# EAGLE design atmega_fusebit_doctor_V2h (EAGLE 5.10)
AUTHOR: PAWEL KISIELEWSKI (MANEKINEN); REV: 2.0
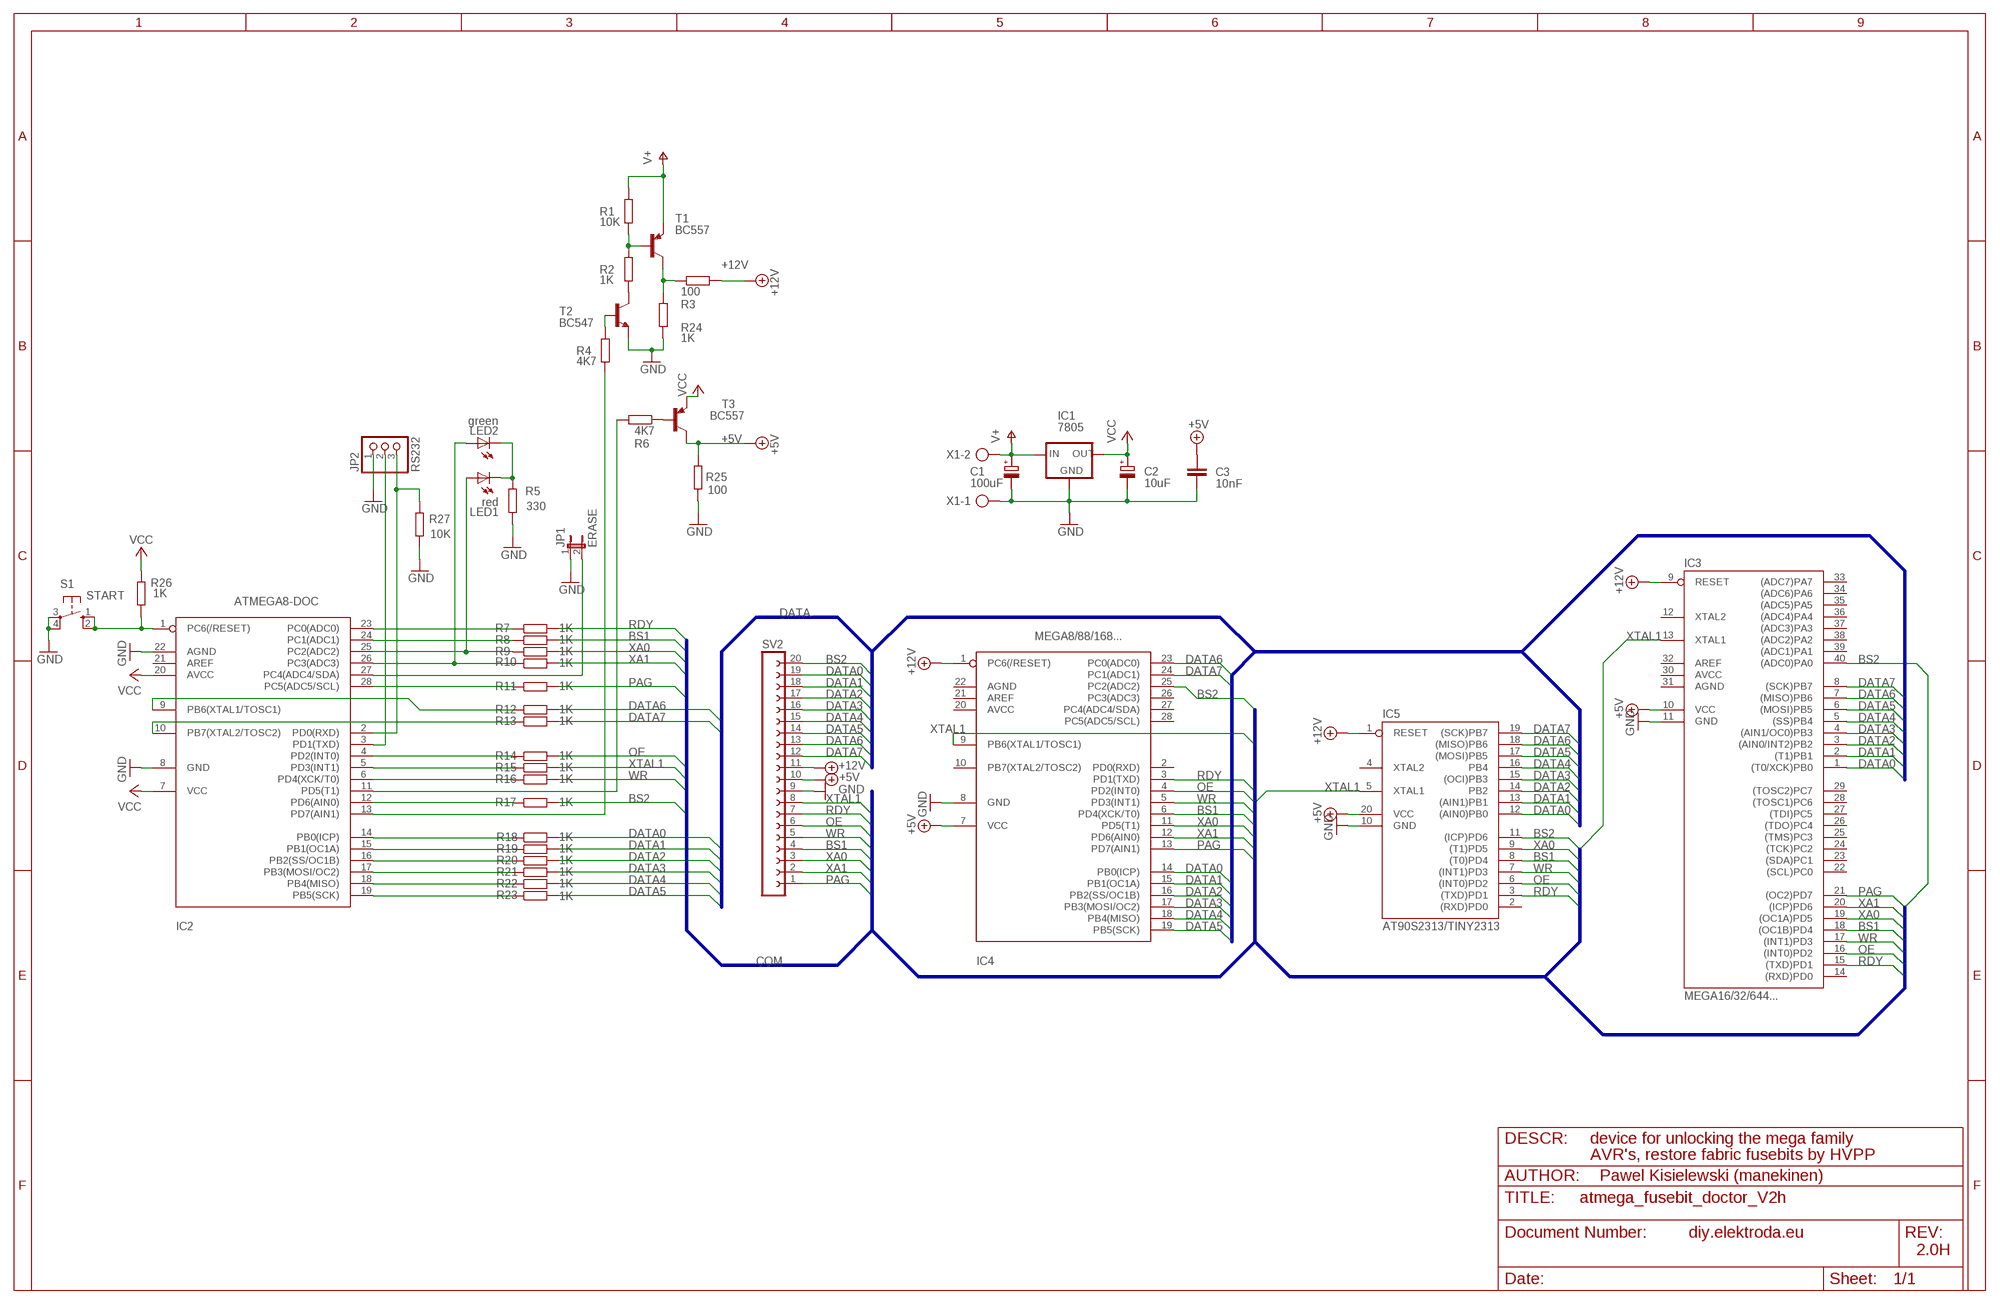
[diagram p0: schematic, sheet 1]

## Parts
C1  100uF  CPOL-EUE2.5-5  [E2,5-5]
C2  10uF  CPOL-EUE2.5-5  [E2,5-5]
C3  10nF  C-EU050-024X044  [C050-024X044]
IC1  7805  78XXL  [78XXL]
IC2  ATMEGA8-DOC  MEGA8-P  [DIL28-3]
IC3  MEGA16/32/644...  MEGA16-P  [DIL40]
IC4  MEGA8/88/168...  MEGA8-P  [DIL28-3]
IC5  AT90S2313/TINY2313  AT90S2313P  [DIL20]
JP1  ERASE  JP1E  [JP1]
JP2  RS232  PINHD-1X3  [1X03]
LED1  red  LED3MM  [LED3MM]
LED2  green  LED3MM  [LED3MM]
R1  10K  R-EU_0204/5  [0204/5]
R2  1K  R-EU_0204/5  [0204/5]
R3  100  R-EU_0204/5  [0204/5]
R4  4K7  R-EU_0204/5  [0204/5]
R5  330  R-EU_0204/5  [0204/5]
R6  4K7  R-EU_0204/5  [0204/5]
R7  1K  R-EU_0204/5  [0204/5]
R8  1K  R-EU_0204/5  [0204/5]
R9  1K  R-EU_0204/5  [0204/5]
R10  1K  R-EU_0204/5  [0204/5]
R11  1K  R-EU_0204/5  [0204/5]
R12  1K  R-EU_0204/5  [0204/5]
R13  1K  R-EU_0204/5  [0204/5]
R14  1K  R-EU_0204/5  [0204/5]
R15  1K  R-EU_0204/5  [0204/5]
R16  1K  R-EU_0204/5  [0204/5]
R17  1K  R-EU_0204/5  [0204/5]
R18  1K  R-EU_0204/5  [0204/5]
R19  1K  R-EU_0204/5  [0204/5]
R20  1K  R-EU_0204/5  [0204/5]
R21  1K  R-EU_0204/5  [0204/5]
R22  1K  R-EU_0204/5  [0204/5]
R23  1K  R-EU_0204/5  [0204/5]
R24  1K  R-EU_0204/5  [0204/5]
R25  100  R-EU_0204/5  [0204/5]
R26  1K  R-EU_0204/5  [0204/5]
R27  10K  R-EU_0204/5  [0204/5]
S1  START  10-XX  [B3F-10XX]
SV2  FE20-1  [FE20]
T1  BC557  BC557C-PNP-TO92-EBC  [TO92-EBC]
T2  BC547  BC547A-NPN-TO92-EBC  [TO92-EBC]
T3  BC557  BC557C-PNP-TO92-EBC  [TO92-EBC]
X1  AK500/2  [AK500/2]

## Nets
+5V: C3.1 IC3.10(VCC) IC4.7(VCC) IC5.20(VCC) R25.2 SV2.10 T3.C
+12V: IC3.9(RESET) IC4.1(PC6(/RESET)) IC5.1(RESET) R3.2 SV2.11
BS1: IC3.18((OC1B)PD4) IC4.6(PD4(XCK/T0)) IC5.8((T0)PD4) R8.2 SV2.4
BS2: IC3.40((ADC0)PA0) IC4.25(PC2(ADC2)) IC5.11((ICP)PD6) R17.2 SV2.20
DATA0: IC3.1((T0/XCK)PB0) IC4.14(PB0(ICP)) IC5.12((AIN0)PB0) R18.2 SV2.19
DATA1: IC3.2((T1)PB1) IC4.15(PB1(OC1A)) IC5.13((AIN1)PB1) R19.2 SV2.18
DATA2: IC3.3((AIN0/INT2)PB2) IC4.16(PB2(SS/OC1B)) IC5.14(PB2) R20.2 SV2.17
DATA3: IC3.4((AIN1/OC0)PB3) IC4.17(PB3(MOSI/OC2)) IC5.15((OCI)PB3) R21.2 SV2.16
DATA4: IC3.5((SS)PB4) IC4.18(PB4(MISO)) IC5.16(PB4) R22.2 SV2.15
DATA5: IC3.6((MOSI)PB5) IC4.19(PB5(SCK)) IC5.17((MOSI)PB5) R23.2 SV2.14
DATA6: IC3.7((MISO)PB6) IC4.23(PC0(ADC0)) IC5.18((MISO)PB6) R12.2 SV2.13
DATA7: IC3.8((SCK)PB7) IC4.24(PC1(ADC1)) IC5.19((SCK)PB7) R13.2 SV2.12
GND: C1.- C2.- C3.2 IC1.GND IC2.8(GND) IC2.22(AGND) IC3.11(GND) IC4.8(GND) IC5.10(GND) JP1.1 JP2.1 R5.1 R24.1 R25.1 R27.2 S1.3(P) S1.4(P1) SV2.9 T2.E X1.1
N$1: R6.1 T3.B
N$2: IC2.14(PB0(ICP)) R18.1
N$3: IC2.3(PD1(TXD)) JP2.2
N$4: IC2.28(PC5(ADC5/SCL)) R11.1
N$5: IC2.6(PD4(XCK/T0)) R16.1
N$6: IC2.4(PD2(INT0)) R14.1
N$7: IC2.2(PD0(RXD)) JP2.3 R27.1
N$8: R2.2 T2.C
N$9: IC2.9(PB6(XTAL1/TOSC1)) R12.1
N$10: IC2.10(PB7(XTAL2/TOSC2)) R13.1
N$11: IC2.13(PD7(AIN1)) R4.2
N$12: IC2.11(PD5(T1)) R6.2
N$14: IC2.15(PB1(OC1A)) R19.1
N$16: IC2.16(PB2(SS/OC1B)) R20.1
N$19: IC2.5(PD3(INT1)) R15.1
N$21: IC2.23(PC0(ADC0)) R7.1
N$22: R3.1 R24.2 T1.C
N$24: IC2.17(PB3(MOSI/OC2)) R21.1
N$25: IC2.18(PB4(MISO)) R22.1
N$26: IC2.19(PB5(SCK)) R23.1
N$27: IC2.12(PD6(AIN0)) R17.1
N$29: R4.1 T2.B
N$31: IC2.27(PC4(ADC4/SDA)) JP1.2
N$32: LED1.K(C) LED2.K(C) R5.2
N$34: R1.2 R2.1 T1.B
N$42: IC2.24(PC1(ADC1)) R8.1
N$43: IC2.1(PC6(/RESET)) R26.1 S1.1(S) S1.2(S1)
N$47: IC2.26(PC3(ADC3)) LED2.A R10.1
N$48: IC2.25(PC2(ADC2)) LED1.A R9.1
OE: IC3.16((INT0)PD2) IC4.4(PD2(INT0)) IC5.6((INT0)PD2) R14.2 SV2.6
PAG: IC3.21((OC2)PD7) IC4.13(PD7(AIN1)) R11.2 SV2.1
RDY: IC3.15((TXD)PD1) IC4.3(PD1(TXD)) IC5.3((TXD)PD1) R7.2 SV2.7
V+: C1.+ IC1.IN R1.1 T1.E X1.2
VCC: C2.+ IC1.OUT IC2.7(VCC) IC2.20(AVCC) R26.2 T3.E
WR: IC3.17((INT1)PD3) IC4.5(PD3(INT1)) IC5.7((INT1)PD3) R16.2 SV2.5
XA0: IC3.19((OC1A)PD5) IC4.11(PD5(T1)) IC5.9((T1)PD5) R9.2 SV2.3
XA1: IC3.20((ICP)PD6) IC4.12(PD6(AIN0)) R10.2 SV2.2
XTAL1: IC3.13(XTAL1) IC4.9(PB6(XTAL1/TOSC1)) IC5.5(XTAL1) R15.2 SV2.8
Unconnected: IC2.21(AREF) IC3.12(XTAL2) IC3.14((RXD)PD0) IC3.22((SCL)PC0) IC3.23((SDA)PC1) IC3.24((TCK)PC2) IC3.25((TMS)PC3) IC3.26((TDO)PC4) IC3.27((TDI)PC5) IC3.28((TOSC1)PC6) IC3.29((TOSC2)PC7) IC3.33((ADC7)PA7) IC3.34((ADC6)PA6) IC3.35((ADC5)PA5) IC3.36((ADC4)PA4) IC3.37((ADC3)PA3) IC3.38((ADC2)PA2) IC3.39((ADC1)PA1) IC4.2(PD0(RXD)) IC4.10(PB7(XTAL2/TOSC2)) IC4.20(AVCC) IC4.21(AREF) IC4.22(AGND) IC4.26(PC3(ADC3)) IC4.27(PC4(ADC4/SDA)) IC4.28(PC5(ADC5/SCL)) IC5.2((RXD)PD0) IC5.4(XTAL2)

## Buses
DATA
COM

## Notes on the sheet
- DESCR: | device for unlocking the mega family
- AVR's, restore fabric fusebits by HVPP
- AUTHOR: | Pawel Kisielewski (manekinen)
- diy.elektroda.eu
- 2.0H

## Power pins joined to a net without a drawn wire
AGND: IC3.31(AGND)
AREF: IC3.32(AREF)
AVCC: IC3.30(AVCC)

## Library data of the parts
C1 C2 = rcl:CPOL-EU: POLARIZED CAPACITOR, European symbol
C3 = rcl:C-EU: CAPACITOR, European symbol
IC1 = v-reg:78XXL: VOLTAGE REGULATOR
IC2 IC4 = atmel:MEGA8-P: MICROCONTROLLER 8 Kbytes FLASH 1 kbytes SRAM 512 bytes EEPROM USART 4-channel 10 bit ADC 2-channel 8 bit ADC Source: avr.lbr
IC3 = atmel:MEGA16-P: MICROCONTROLLER 16 Kbytes FLASH 1 kbytes SRAM 512 bytes EEPROM USART 8-channel 10 bit ADC Source: avr.lbr
IC5 = atmel:AT90S2313: MICROCONTROLLER 2 Kbytes FLASH 128 bytes SRAM 128 bytes EEPROM UART
JP1 = jumper:JP1E: JUMPER
JP2 = pinhead:PINHD-1X3: PIN HEADER
LED1 LED2 = led:LED: LED
R1-R27 = rcl:R-EU_: RESISTOR, European symbol
S1 = switch-omron:10-XX: OMRON SWITCH
SV2 = con-lsta:FE20-1: FEMALE HEADER
T1 T3 = transistor:*-PNP-: PNP Transistror
T2 = transistor:*-NPN-: NPN Transistror
X1 = con-ptr500:AK500/2: CONNECTOR

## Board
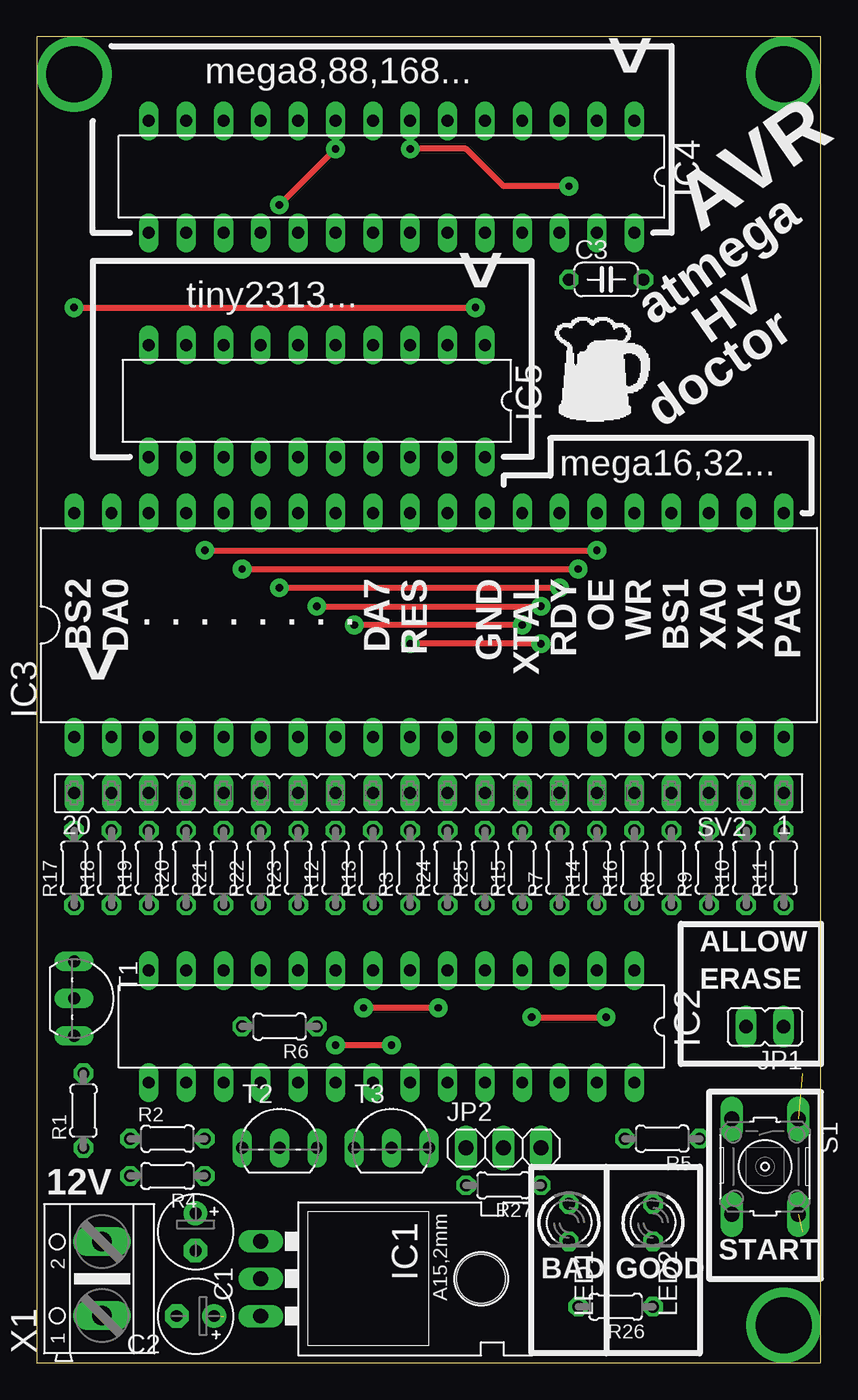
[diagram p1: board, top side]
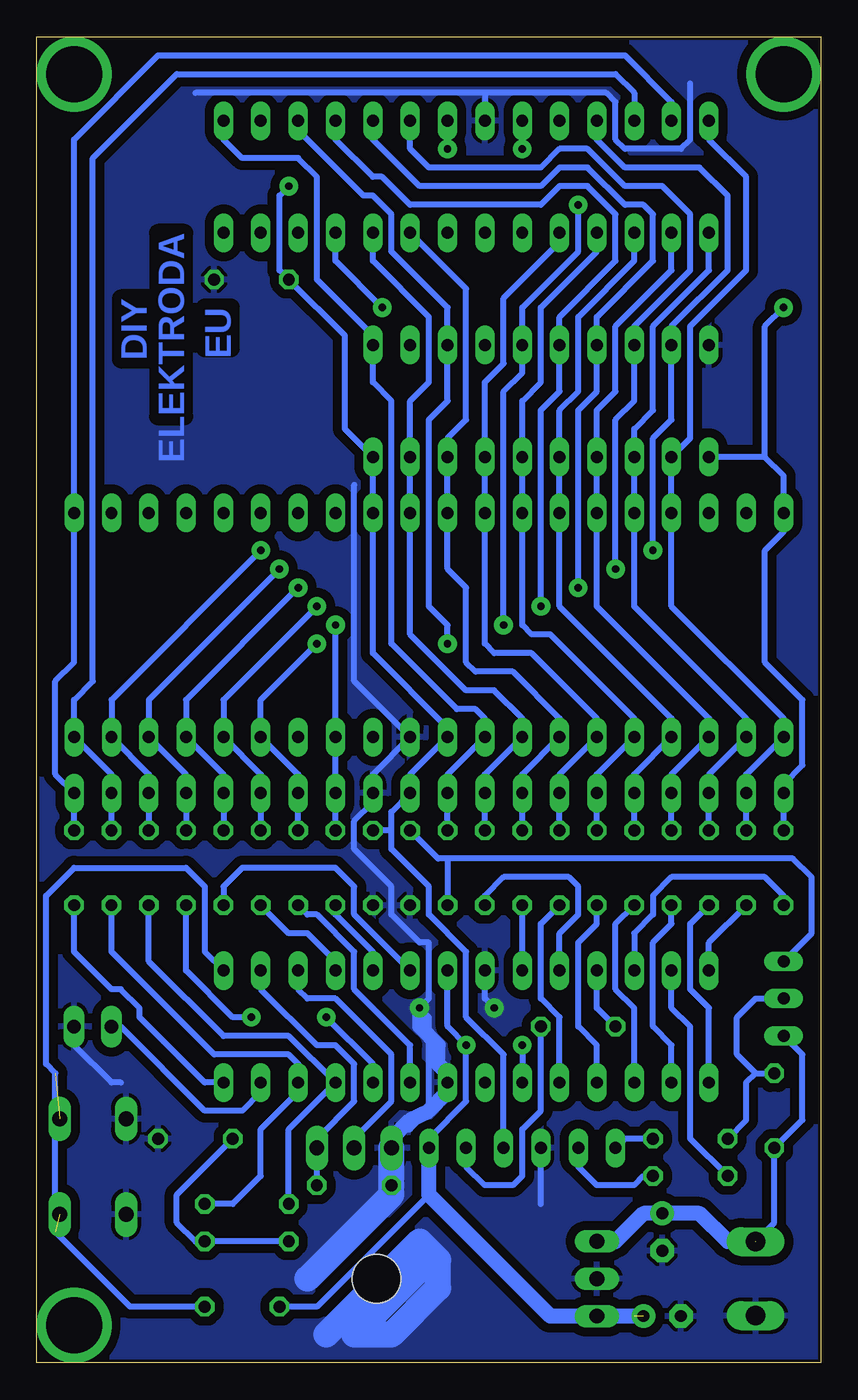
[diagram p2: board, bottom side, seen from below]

Size 53.33 x 90.16 mm. Coordinates in mm from the lower left corner, seen from the top.
Outline: 0,90.16 0,0 53.33,0 53.33,90.16 0,90.16
Copper layers (1*16): Top 0.035mm / dielectric 1.5mm / Bottom 0.035mm
Design rules "default *": minimum track width 10mil, minimum drill 24mil, track to track 24mil, track to pad 24mil, pad to pad 8mil, via to via 8mil, smd to smd 8mil, copper to edge 8mil, drill to drill 8mil, minimum pad ring 10mil, minimum via ring 8mil, stop-mask expansion 4mil, vias tented up to drill 0mil, thermal gap 10mil

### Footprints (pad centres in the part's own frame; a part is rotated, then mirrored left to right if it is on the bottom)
E2,5-5 = drill 0.813 pad 1.6 round: + -1.27,0 | drill 0.813 pad 1.6 octagon: - 1.27,0
C050-024X044 = drill 0.813 octagon: 1 -2.54,0; 2 2.54,0
78XXL = drill 1.016 long: GND 0,-3.81; IN -2.54,-3.81; OUT 2.54,-3.81 | hole 3.302: 0,11.176
DIL28-3 = drill 0.813 long: 1 -16.51,-3.81; 2 -13.97,-3.81; 3 -11.43,-3.81; 4 -8.89,-3.81; 5 -6.35,-3.81; 6 -3.81,-3.81; 7 -1.27,-3.81; 8 1.27,-3.81; 9 3.81,-3.81; 10 6.35,-3.81; 11 8.89,-3.81; 12 11.43,-3.81; 13 13.97,-3.81; 14 16.51,-3.81; 15 16.51,3.81; 16 13.97,3.81; 17 11.43,3.81; 18 8.89,3.81; 19 6.35,3.81; 20 3.81,3.81; 21 1.27,3.81; 22 -1.27,3.81; 23 -3.81,3.81; 24 -6.35,3.81; 25 -8.89,3.81; 26 -11.43,3.81; 27 -13.97,3.81; 28 -16.51,3.81
DIL40 = drill 0.813 long: 1 -24.13,-7.62; 2 -21.59,-7.62; 3 -19.05,-7.62; 4 -16.51,-7.62; 5 -13.97,-7.62; 6 -11.43,-7.62; 7 -8.89,-7.62; 8 -6.35,-7.62; 9 -3.81,-7.62; 10 -1.27,-7.62; 11 1.27,-7.62; 12 3.81,-7.62; 13 6.35,-7.62; 14 8.89,-7.62; 15 11.43,-7.62; 16 13.97,-7.62; 17 16.51,-7.62; 18 19.05,-7.62; 19 21.59,-7.62; 20 24.13,-7.62; 21 24.13,7.62; 22 21.59,7.62; 23 19.05,7.62; 24 16.51,7.62; 25 13.97,7.62; 26 11.43,7.62; 27 8.89,7.62; 28 6.35,7.62; 29 3.81,7.62; 30 1.27,7.62; 31 -1.27,7.62; 32 -3.81,7.62; 33 -6.35,7.62; 34 -8.89,7.62; 35 -11.43,7.62; 36 -13.97,7.62; 37 -16.51,7.62; 38 -19.05,7.62; 39 -21.59,7.62; 40 -24.13,7.62
DIL20 = drill 0.813 long: 1 -11.43,-3.81; 2 -8.89,-3.81; 3 -6.35,-3.81; 4 -3.81,-3.81; 5 -1.27,-3.81; 6 1.27,-3.81; 7 3.81,-3.81; 8 6.35,-3.81; 9 8.89,-3.81; 10 11.43,-3.81; 11 11.43,3.81; 12 8.89,3.81; 13 6.35,3.81; 14 3.81,3.81; 15 1.27,3.81; 16 -1.27,3.81; 17 -3.81,3.81; 18 -6.35,3.81; 19 -8.89,3.81; 20 -11.43,3.81
JP1 = drill 0.914 long: 1 0,-1.27; 2 0,1.27
1X03 = drill 1.016 long: 1 -2.54,0; 2 0,0; 3 2.54,0
LED3MM = drill 0.813 octagon: A -1.27,0; K 1.27,0
0204/5 = drill 0.813 octagon: 1 -2.54,0; 2 2.54,0
B3F-10XX = drill 1.016 long: 1 -3.251,2.261; 2 3.251,2.261; 3 -3.251,-2.261; 4 3.251,-2.261
FE20 = drill 0.813 long: 1 -24.13,0; 2 -21.59,0; 3 -19.05,0; 4 -16.51,0; 5 -13.97,0; 6 -11.43,0; 7 -8.89,0; 8 -6.35,0; 9 -3.81,0; 10 -1.27,0; 11 1.27,0; 12 3.81,0; 13 6.35,0; 14 8.89,0; 15 11.43,0; 16 13.97,0; 17 16.51,0; 18 19.05,0; 19 21.59,0; 20 24.13,0
TO92-EBC = drill 0.813 long: B 0,-1.27; C -2.54,-1.27; E 2.54,-1.27
AK500/2 = drill 1.321 long: 1 -2.515,0; 2 2.515,0

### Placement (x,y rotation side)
C1  10.79,8.88 270 top
C2  10.79,3.17 180 top
C3  38.73,73.65 0 top
IC1  19.05,5.71 270 top
IC2  24.13,22.85 180 top
IC3  26.67,50.16 0 top
IC4  24.13,80.64 180 top
IC5  19.05,65.39 180 top
JP1  49.53,22.85 90 top
JP2  31.75,14.59 0 top
LED1  36.2,9.52 270 top
LED2  41.91,9.52 270 top
R1  3.17,17.14 90 top
R2  8.89,15.23 0 top
R3  25.4,33.65 90 top
R4  8.89,12.69 180 top
R5  42.55,15.23 180 top
R6  16.51,22.85 180 top
R7  35.56,33.65 90 top
R8  43.18,33.65 90 top
R9  45.72,33.65 90 top
R10  48.26,33.65 90 top
R11  50.8,33.65 90 top
R12  20.32,33.65 90 top
R13  22.86,33.65 90 top
R14  38.1,33.65 90 top
R15  33.02,33.65 90 top
R16  40.64,33.65 90 top
R17  2.54,33.65 90 top
R18  5.08,33.65 90 top
R19  7.62,33.65 90 top
R20  10.16,33.65 90 top
R21  12.7,33.65 90 top
R22  15.24,33.65 90 top
R23  17.78,33.65 90 top
R24  27.94,33.65 90 top
R25  30.48,33.65 90 top
R26  39.37,3.8 180 top
R27  31.75,12.05 180 top
S1  49.53,13.32 270 top
SV2  26.67,38.73 180 top
T1  3.81,24.75 270 top
T2  16.51,15.86 0 top
T3  24.13,15.86 0 top
X1  4.45,5.71 90 top

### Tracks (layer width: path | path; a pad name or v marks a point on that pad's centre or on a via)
+5V  (via drill 0.5 pad 1.27)
  Top 0.406: v36.2,80 31.75,80 29.21,82.54 v25.4,82.54
  Bottom 0.406: v25.4,82.54 IC4.7 | v36.2,80 36.83,79.37 36.83,74.29 C3.1 32.38,69.84 32.38,63.49 IC5.20 30.48,48.25 25.4,43.17 IC3.10 27.94,39.99 SV2.10 29.21,37.45 29.21,36.19 | 29.21,36.19 29.21,34.91 26.67,32.38 26.67,30.47 24.13,27.93 24.13,23.48 21.59,20.95 T3.C | 29.21,36.19 R25.2
+12V
  Bottom 0.406: IC4.1 40.64,83.18 39.37,81.91 35.56,81.91 34.29,80.64 34.29,73.65 30.48,69.84 IC5.1 30.48,66.67 29.21,65.39 29.21,48.88 24.77,44.44 23.5,44.44 22.86,43.8 IC3.9 25.4,39.99 SV2.11 | SV2.11 25.4,38.09 | R3.2 SV2.11
BS1  (via drill 0.5 pad 1.27)
  Top 0.406: v13.97,53.96 v36.83,53.96
  Bottom 0.406: IC4.6 27.94,82.54 26.67,81.27 19.05,81.27 17.78,82.54 15.88,82.54 13.34,80 10.79,80 8.89,78.1 8.89,74.29 12.7,70.48 IC5.8 12.7,65.39 13.97,64.12 v13.97,53.96 | v36.83,53.96 45.72,45.07 IC3.18 43.18,39.99 SV2.4 R8.2
BS2  (via drill 0.5 pad 1.27)
  Top 0.406: v2.54,71.75 v29.84,71.75
  Bottom 0.406: v2.54,71.75 3.81,70.48 3.81,61.59 | IC4.25 33.02,74.92 v29.84,71.75 | 3.81,61.59 2.54,60.31 IC3.40 2.54,56.51 3.81,55.23 3.81,47.62 1.27,45.07 1.27,40.63 2.54,39.36 SV2.20 R17.2 | 3.81,61.59 IC5.11
DATA0
  Bottom 0.406: IC4.14 7.62,83.18 5.08,80.64 5.08,74.29 8.89,70.48 8.89,62.85 IC5.12 10.16,51.42 2.54,43.8 IC3.1 5.08,39.99 SV2.19 R18.2
DATA1
  Bottom 0.406: IC4.15 7.62,74.29 11.43,70.48 11.43,64.76 12.7,63.49 IC5.13 12.7,51.42 5.08,43.8 IC3.2 7.62,39.99 SV2.18 R19.2
DATA2
  Bottom 0.406: IC4.16 10.16,74.29 13.97,70.48 13.97,66.03 15.24,64.76 IC5.14 15.24,51.42 7.62,43.8 IC3.3 10.16,39.99 SV2.17 R20.2
DATA3
  Bottom 0.406: IC4.17 12.7,74.92 16.51,71.11 16.51,66.03 17.78,64.76 IC5.15 17.78,51.42 10.16,43.8 IC3.4 12.7,39.99 SV2.16 R21.2
DATA4
  Bottom 0.406: IC4.18 15.24,75.56 19.05,71.75 19.05,66.67 20.32,65.39 IC5.16 20.32,50.16 19.68,49.52 18.41,49.52 12.7,43.8 IC3.5 15.24,39.99 SV2.15 R22.2
DATA5
  Bottom 0.406: IC4.19 17.78,76.19 21.59,72.38 21.59,67.94 22.86,66.67 IC5.17 22.86,48.88 22.23,48.25 19.68,48.25 15.24,43.8 IC3.6 17.78,39.99 SV2.14 R23.2
DATA6
  Bottom 0.406: IC4.23 24.13,73.02 24.13,64.12 25.4,62.85 IC5.18 25.4,53.96 24.13,52.7 24.13,47.62 23.5,46.98 20.95,46.98 17.78,43.8 IC3.7 20.32,39.99 SV2.13 R12.2
DATA7
  Bottom 0.406: IC4.24 30.48,74.92 26.67,71.11 26.67,66.67 27.94,65.39 IC5.19 27.94,49.52 24.13,45.71 22.23,45.71 20.32,43.8 IC3.8 22.86,39.99 SV2.12 R13.2
GND  (via drill 0.5 pad 1.27)
  Top 0.406: v27.3,24.12 v22.23,24.12
  Bottom 0.406: 31.75,59.68 31.75,46.34 IC3.11 30.48,39.99 SV2.9 30.48,38.09 31.75,36.82 31.75,34.91 29.21,32.38 29.21,30.47 27.3,28.56 26.67,28.56 26.67,24.75 v27.3,24.12 26.67,23.48 26.67,17.14 27.94,15.86 29.21,15.86 JP2.1 | 8.89,86.98 8.89,83.18 9.53,82.54 13.34,82.54 13.97,83.18 13.97,85.72 14.61,86.35 22.86,86.35 | v22.23,24.12 22.86,24.75 IC2.8 | 22.86,86.35 IC4.8 | 22.86,86.35 42.55,86.35 | 19.05,10.79 T2.E | JP1.1 50.8,21.58 48.26,19.04 47.62,19.04
  Bottom 1.016: JP2.1 29.21,15.23 27.94,16.5 26.67,17.14 25.4,18.41 IC2.22 25.4,19.68 26.04,20.31 26.04,21.58 27.3,22.85 v27.3,24.12
  Bottom 1.778: JP2.1 29.21,11.42 34.92,5.71 | 33.66,1.9 27.3,8.25 26.04,6.97 26.04,5.07 29.21,1.9 31.75,1.9 27.3,6.34
  pour Bottom: 53.34,90.16 0,90.16 0,-0.01 53.34,-0.01
N$1
  Bottom 0.406: R6.1 19.05,17.14 20.32,15.86 20.32,12.69 20.95,12.05 22.86,12.05 24.13,13.32 T3.B
N$2
  Bottom 0.406: R18.1 7.62,28.56 IC2.14
N$3
  Bottom 0.406: IC2.3 35.56,25.39 34.92,24.75 33.02,24.75 29.21,20.95 29.21,17.77 31.75,15.23 JP2.2
N$4
  Bottom 0.406: R11.1 50.8,27.93 48.26,25.39 47.62,25.39 46.35,24.12 46.35,23.48 41.91,19.04 IC2.28
N$5
  Bottom 0.406: R16.1 40.64,32.38 39.37,33.65 33.02,33.65 31.75,32.38 31.75,30.47 IC2.6
N$6
  Bottom 0.406: R14.1 36.2,29.2 34.92,29.2 33.02,27.29 IC2.4
N$7
  Bottom 0.406: IC2.2 38.1,25.39 34.29,21.58 33.02,21.58 31.75,20.31 31.75,17.77 34.29,15.23 JP2.3 R27.1
N$8
  Bottom 0.406: R2.2 13.34,15.23 T2.C
N$9
  Bottom 0.406: IC2.9 R12.1
N$10
  Bottom 0.406: IC2.10 17.78,29.2 16.51,30.47 16.51,32.38 17.14,33.01 21.59,33.01 22.86,31.74 R13.1
N$11
  Bottom 0.406: R4.2 8.89,15.23 8.89,22.85 10.16,24.12 IC2.13
N$12
  Bottom 0.406: R6.2 15.24,24.12 IC2.11
N$13  (via drill 3.81 pad 5.08)
  other vias: 50.8,2.53
N$14
  Bottom 0.406: R19.1 8.89,29.84 8.89,25.39 7.62,24.12 IC2.15
N$15  (via drill 3.81 pad 5.08)
  other vias: 50.8,87.62
N$16
  Bottom 0.406: R20.1 10.16,29.84 11.43,28.56 11.43,22.85 10.16,21.58 IC2.16
N$17  (via drill 3.81 pad 5.08)
  other vias: 2.54,87.62
N$19
  Bottom 0.406: R15.1 33.02,30.47 30.48,27.93 IC2.5
N$21
  Bottom 0.406: R7.1 34.92,30.47 34.29,30.47 31.75,27.93 31.75,25.39 27.94,21.58 IC2.23
N$22
  Bottom 0.406: 25.4,34.28 R3.1 | 25.4,34.28 1.91,34.28 0.64,33.01 0.64,29.2 T1.C | 25.4,34.28 26.04,34.28 R24.2
N$24
  Bottom 0.406: R21.1 13.97,29.84 13.97,25.39 12.7,24.12 IC2.17
N$25
  Bottom 0.406: R22.1 15.24,29.84 16.51,28.56 16.51,22.85 15.24,21.58 IC2.18
N$26
  Bottom 0.406: R23.1 19.05,29.84 19.05,24.75 17.78,23.48 IC2.19
N$27
  Bottom 0.406: R17.1 2.54,31.74 3.81,33.01 10.16,33.01 11.43,31.74 11.43,30.47 12.7,29.2 IC2.12
N$29
  Bottom 0.406: R4.1 12.06,12.69 12.7,12.05 15.24,12.05 16.51,13.32 T2.B
N$31
  Bottom 0.406: IC2.27 38.1,18.41 39.37,17.14 41.91,17.14 47.62,22.85 JP1.2
N$32
  Bottom 0.406: LED2.K LED1.K LED2.K | LED2.K 42.55,8.25 43.81,9.52 43.81,11.42 R5.2
N$34
  Bottom 0.406: T1.B 4.45,24.75 5.71,23.48 5.71,20.95 4.45,19.68 | R2.1 5.08,16.5 5.08,19.04 4.45,19.68 | 4.45,19.68 R1.2
N$42  (via drill 0.5 pad 1.27)
  Top 0.406: v33.66,23.48 v38.73,23.48
  Bottom 0.406: R8.1 43.18,26.66 40.01,23.48 v38.73,23.48 | v33.66,23.48 30.48,20.31 IC2.24
N$43  (2 unrouted)
  Bottom 0.406: IC2.1 41.91,27.93 41.91,32.38 43.18,33.65 50.8,33.65 52.7,31.74 52.7,20.31 52.07,19.68 52.07,8.88 46.99,3.8 R26.1
N$47
  Bottom 0.406: LED2.A 40.01,10.79 38.1,12.69 38.1,15.86 35.56,18.41 IC2.26 35.56,20.31 36.2,20.95 41.27,20.95 48.26,27.93 R10.1
N$48
  Bottom 0.406: R9.1 45.72,27.29 40.64,22.21 36.2,22.21 IC2.25 36.2,15.86 LED1.A
OE  (via drill 0.5 pad 1.27)
  Top 0.406: v19.05,51.42 v34.29,51.42
  Bottom 0.406: IC4.4 33.02,83.18 30.48,80.64 29.84,80.64 27.94,78.73 19.05,78.73 17.78,80 15.88,80 13.97,78.1 13.97,74.92 17.78,71.11 IC5.6 17.78,66.03 19.05,64.76 v19.05,51.42 | v34.29,51.42 40.64,45.07 IC3.16 38.1,39.99 SV2.6 R14.2
PAG
  Bottom 0.406: IC4.13 10.16,85.72 13.34,88.89 45.09,88.89 50.8,83.18 IC3.21 50.8,47.62 52.07,46.34 52.07,39.99 SV2.1 R11.2
RDY  (via drill 0.5 pad 1.27)
  Top 0.406: v34.29,48.88 v25.4,48.88
  Bottom 0.406: IC4.3 35.56,83.81 31.11,79.37 30.48,79.37 29.21,78.1 29.21,75.56 25.4,71.75 IC5.3 25.4,65.39 26.67,64.12 26.67,51.42 25.4,50.16 v25.4,48.88 | v34.29,48.88 38.1,45.07 IC3.15 35.56,39.99 SV2.7 R7.2
V+  (1 unrouted)
  Bottom 0.406: T1.E 1.27,20.95 1.27,16.5 R1.1 3.17,9.52 4.45,8.25
  Bottom 1.016: 4.45,8.25 6.35,8.25 8.26,10.15 C1.+ 12.06,10.15 13.97,8.25 IC1.IN
VCC  (via drill 0.5 pad 1.27)  (1 unrouted)
  Top 0.406: v24.13,21.58 v20.32,21.58
  Bottom 0.406: IC2.7 25.4,22.85 v24.13,21.58 24.13,17.77 26.67,15.23 T3.E | v20.32,21.58 IC2.20 | R26.2 34.29,3.8 26.67,11.42
  Bottom 1.016: T3.E 26.67,11.42 18.41,3.17 IC1.OUT 12.7,3.17
WR  (via drill 0.5 pad 1.27)
  Top 0.406: v16.51,52.7 v35.56,52.7
  Bottom 0.406: v16.51,52.7 16.51,64.76 15.24,66.03 IC5.7 15.24,71.11 11.43,74.92 11.43,78.1 12.06,78.73 13.34,78.73 15.88,81.27 17.78,81.27 19.05,80 27.3,80 30.48,83.18 IC4.5 | v35.56,52.7 43.18,45.07 IC3.17 40.64,39.99 SV2.5 R16.2
XA0  (via drill 0.5 pad 1.27)
  Top 0.406: v11.43,55.23 v38.1,55.23
  Bottom 0.406: IC4.11 15.24,83.18 13.34,81.27 8.26,81.27 6.35,79.37 6.35,74.29 10.16,70.48 IC5.9 10.16,64.12 11.43,62.85 v11.43,55.23 | v38.1,55.23 48.26,45.07 IC3.19 45.72,39.99 SV2.3 R9.2
XA1
  Bottom 0.406: IC4.12 12.7,86.35 13.97,87.62 43.81,87.62 49.53,81.91 49.53,46.34 50.8,45.07 IC3.20 48.26,39.99 SV2.2 R10.2
XTAL1  (via drill 0.5 pad 1.27)
  Top 0.406: v16.51,78.73 v20.32,82.54 | v33.02,50.16 v21.59,50.16
  Bottom 0.406: v20.32,82.54 IC4.9 | v16.51,78.73 16.51,75.56 20.32,71.75 IC5.5 20.32,67.3 21.59,66.03 v21.59,50.16 | v33.02,50.16 IC3.13 SV2.8 R15.2

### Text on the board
Bottom: ELEKTRODA | EU | DIY
tPlace: ^ | mega8,88,168... | ^ | AVR | tiny2313... | atmega | HV | doctor | mega16,32... | BS2 | DA0 | DA7 | RES | GND | XTAL | RDY | OE | WR | BS1 | XA0 | XA1 | PAG | ^ | . . . . . . . . | ALLOW | ERASE | 12V | START | BAD | GOOD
